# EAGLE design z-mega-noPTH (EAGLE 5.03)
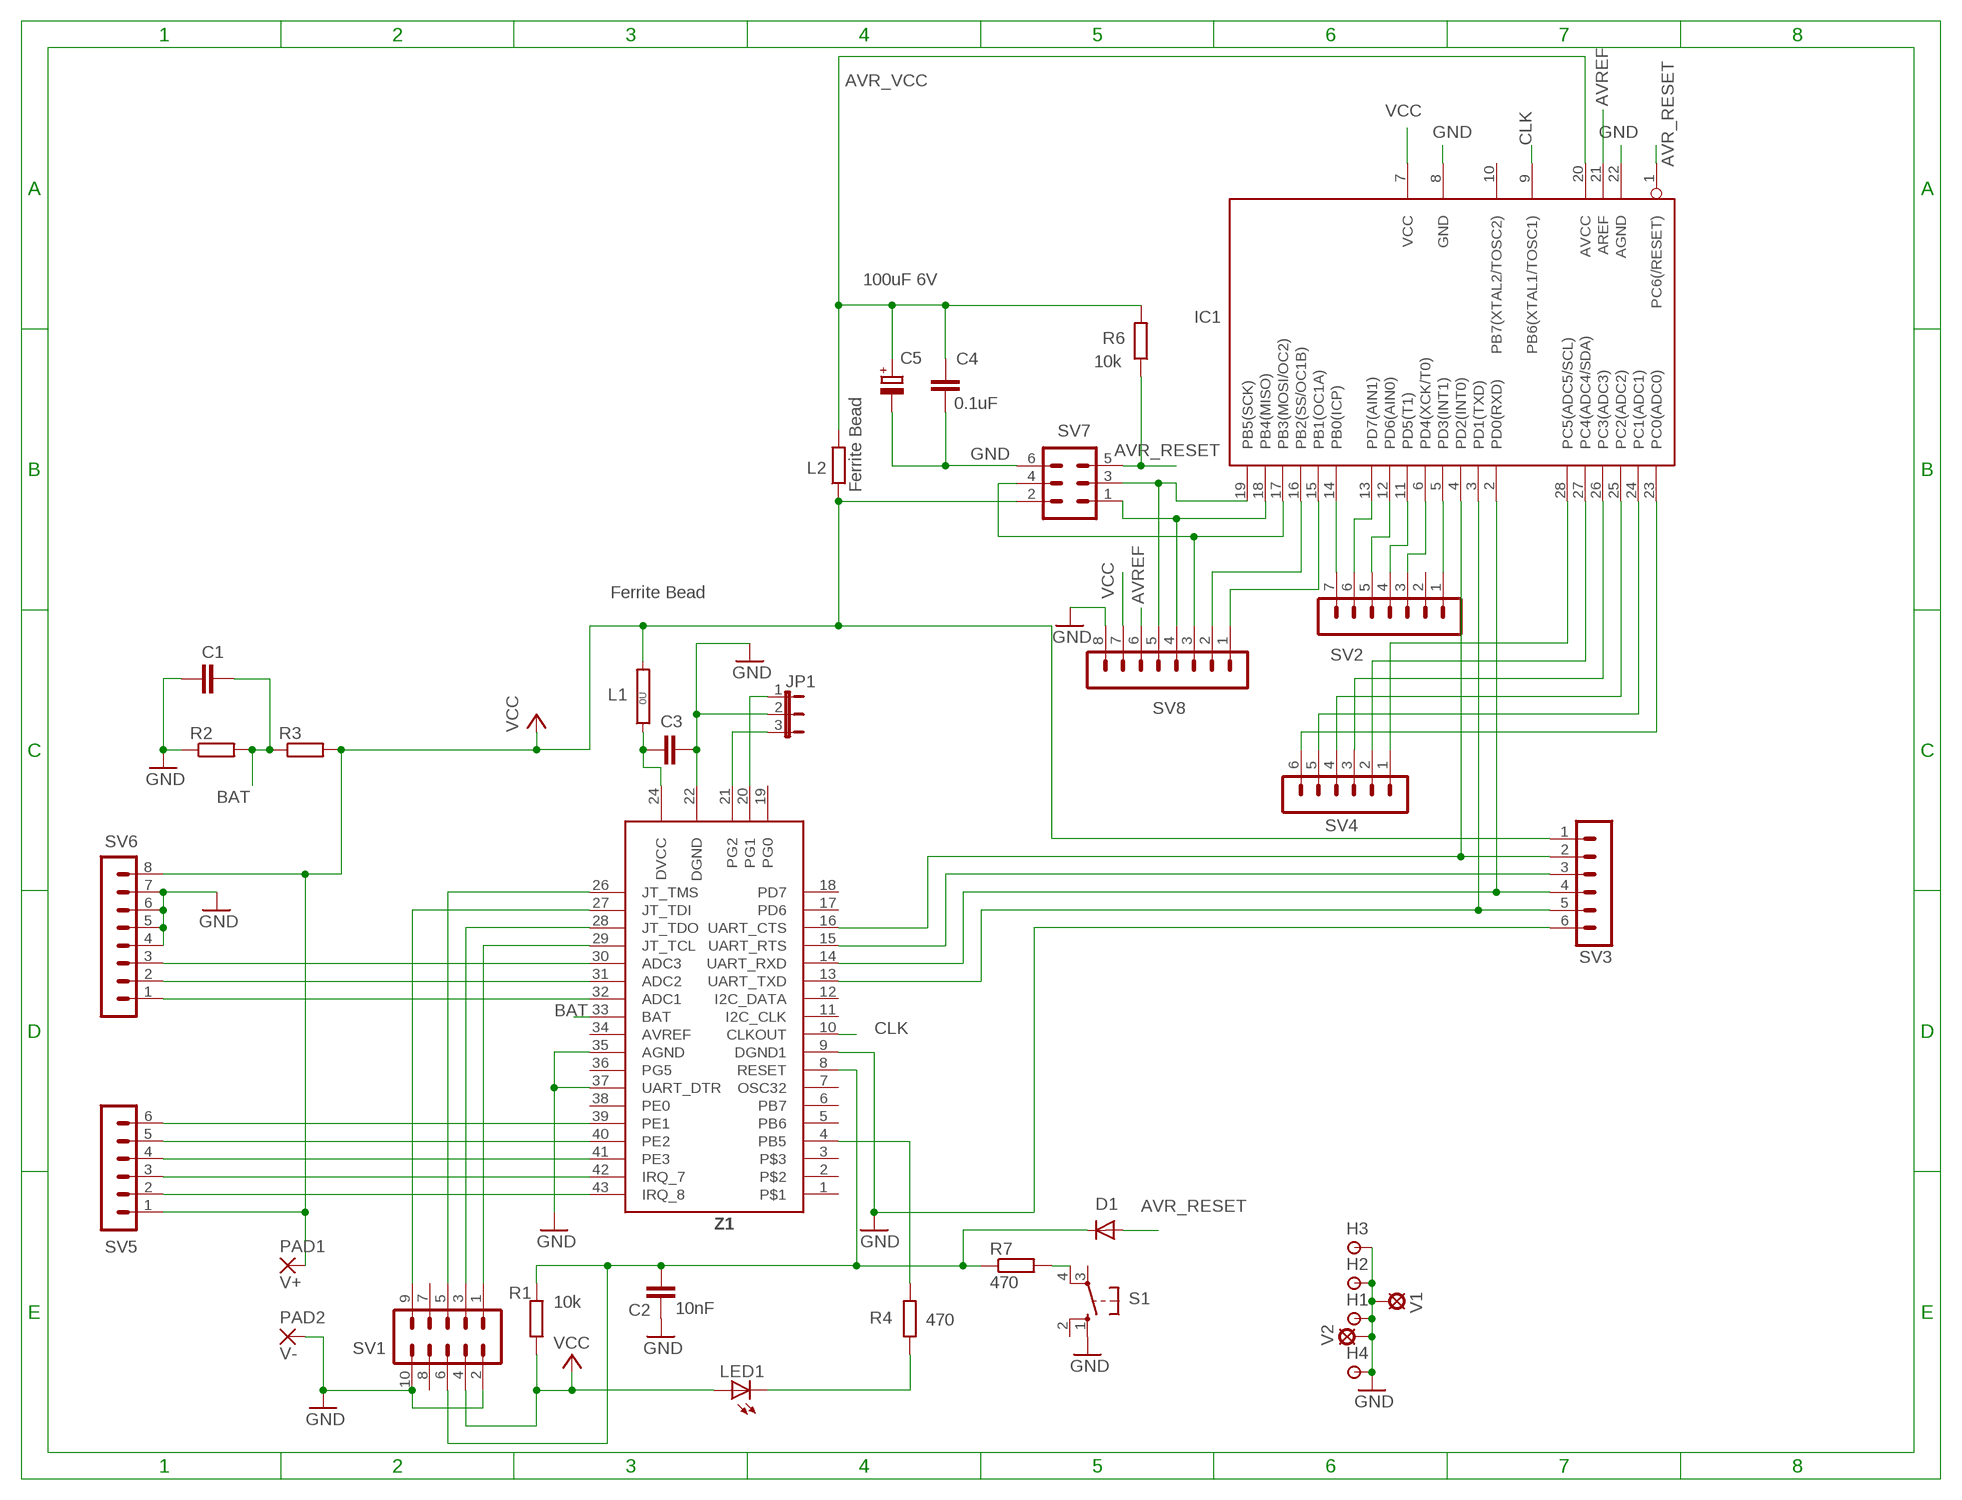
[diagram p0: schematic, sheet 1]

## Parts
C1  0.1uF  C5P  [C050-030-075]
C2  10nF  C5P  [C050-030-075]
C3  10uF 10V ceramic  CSMT0805  [C0805]
C4  0.1uF  C2.5P  [C025-030X050]
C5  100uF 6V  CPOL1  [E2,5-7---100UF]
D1  1N4148  DIODE-DO07  [DO07]
H1  HOLE/SMALL  [1,6/0,8]
H2  HOLE/SMALL  [1,6/0,8]
H3  HOLE/SMALL  [1,6/0,8]
H4  HOLE/SMALL  [1,6/0,8]
IC1  MEGA8-P  [DIL28-3]
JP1  3 way pin header with jumper  JP2E  [JP2]
L1  Ferrite Bead  0R  [0R/10]
L2  Ferrite Bead  R  [0207/10]
LED1  LED-3MM3MM  [HLMP-D105]
PAD1  V+  TERMINAL-PAD  [2,54/1,1]
PAD2  V-  TERMINAL-PAD  [2,54/1,1]
R1  10k  R  [0207/10]
R2  11k  R  [0207/10]
R3  22k  R  [0207/10]
R4  470  R  [0207/10]
R6  10k  R  [0207/10]
R7  470  R  [0207/10]
S1  PCB pushbutton BW3-1000  10-XX  [B3F-10XX]
SV1  10 way IDC male header  ML10  [ML10]
SV2  7 way header top side  MA07-1  [MA07-1]
SV3  6 way pin header top side, soldered both sides  MA06-1  [MA06-1]
SV4  6 way pin header top side  MA06-1  [MA06-1]
SV5  5 way pin header bottom mnt  MA06-1  [MA06-1]
SV6  8 way pin header bottom mnt  MA08-1  [MA08-1]
SV7  6 way male IDC header  ML6  [ML6]
SV8  8 way pin header top side  MA08-1  [MA08-1]
V1  HOLE/VIA  [LSP10]
V2  HOLE-VIA  [LSP10]
Z1  ZDM-A1281-A2N  [ZIGSMD]

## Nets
AVR_RESET: D1.A IC1.1(PC6(/RESET)) R6.1 SV7.5
AVR_VCC: C4.1 C5.+ IC1.20(AVCC) L2.2 R6.2
AVREF: IC1.21(AREF) SV8.6
BAT: C1.2 R2.2 R3.1 Z1.33(BAT)
CLK: IC1.9(PB6(XTAL1/TOSC1)) Z1.10(CLKOUT)
GND [supply]: C1.1 C2.1 C3.2 C4.2 C5.- H1.1(P) H2.1(P) H3.1(P) H4.1(P) IC1.8(GND) IC1.22(AGND) JP1.2 PAD2.1(P) R2.1 S1.1(S) SV1.2 SV1.10 SV3.6 SV6.4 SV6.5 SV6.6 SV6.7 SV7.6 SV8.8 V1.MP V2.MP Z1.9(DGND1) Z1.22(DGND) Z1.35(AGND) Z1.37(UART_DTR)
N$1: IC1.18(PB4(MISO)) SV7.1 SV8.4
N$2: IC1.19(PB5(SCK)) SV7.3 SV8.5
N$3: SV6.2 Z1.31(ADC2)
N$4: SV6.3 Z1.30(ADC3)
N$5: SV6.1 Z1.32(ADC1)
N$6: R7.2 S1.4(P1)
N$7: SV5.4 Z1.41(PE3)
N$8: IC1.17(PB3(MOSI/OC2)) SV7.4 SV8.3
N$9: SV1.5 Z1.26(JT_TMS)
N$10: SV1.1 Z1.29(JT_TCL)
N$11: SV1.3 Z1.28(JT_TDO)
N$12: SV5.6 Z1.39(PE1)
N$13: C2.2 D1.C R1.2 R7.1 SV1.6 Z1.8(RESET)
N$14: SV5.3 Z1.42(IRQ_7)
N$15: SV5.2 Z1.43(IRQ_8)
N$16: IC1.23(PC0(ADC0)) SV4.6
N$17: IC1.24(PC1(ADC1)) SV4.5
N$18: IC1.4(PD2(INT0)) SV3.2 Z1.16(UART_CTS)
N$19: SV3.3 Z1.15(UART_RTS)
N$20: IC1.2(PD0(RXD)) SV3.4 Z1.14(UART_RXD)
N$21: IC1.3(PD1(TXD)) SV3.5 Z1.13(UART_TXD)
N$24: IC1.25(PC2(ADC2)) SV4.4
N$25: JP1.1 Z1.20(PG1)
N$28: R4.2 Z1.4(PB5)
N$29: JP1.3 Z1.21(PG2)
N$30: LED1.K(C) R4.1
N$31: SV1.9 Z1.27(JT_TDI)
N$32: SV5.5 Z1.40(PE2)
N$33 [supply]: C3.1 L1.1 Z1.24(DVCC)
N$34: IC1.26(PC3(ADC3)) SV4.3
N$35: IC1.27(PC4(ADC4/SDA)) SV4.2
N$36: IC1.28(PC5(ADC5/SCL)) SV4.1
N$37: IC1.5(PD3(INT1)) SV2.1
N$38: IC1.15(PB1(OC1A)) SV8.1
N$39: IC1.16(PB2(SS/OC1B)) SV8.2
N$40: IC1.12(PD6(AIN0)) SV2.5
N$41: IC1.13(PD7(AIN1)) SV2.6
N$42: IC1.14(PB0(ICP)) SV2.7
N$44: IC1.6(PD4(XCK/T0)) SV2.3
N$45: IC1.11(PD5(T1)) SV2.4
VCC: IC1.7(VCC) L1.2 L2.1 LED1.A PAD1.1(P) R1.1 R3.2 SV1.4 SV3.1 SV5.1 SV6.8 SV7.2 SV8.7
Unconnected: IC1.10(PB7(XTAL2/TOSC2)) S1.2(S1) S1.3(P) SV1.7 SV1.8 SV2.2 Z1.1 Z1.2 Z1.3 Z1.5(PB6) Z1.6(PB7) Z1.7(OSC32) Z1.11(I2C_CLK) Z1.12(I2C_DATA) Z1.17(PD6) Z1.18(PD7) Z1.19(PG0) Z1.34(AVREF) Z1.36(PG5) Z1.38(PE0)

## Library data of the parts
C1-C4 = ee2parts:C: Capacitor
C5 = ee2parts:CPOL: Electrolytic (polarised) capacitor
D1 = diode:DIODE-: DIODE
H1-H4 = ee2parts:HOLE/SMALL: SMALL THROUGH-HOLE PAD/TESTPOINT
IC1 = atmel:MEGA8-P: MICROCONTROLLER 8 Kbytes FLASH, 1 kbytes SRAM, 512 bytes EEPROM, USART, 4-channel 10 bit ADC, 2-channel 8 bit ADC Pin compatible with Atmega48, ATMega88, ATMega168 Source: avr.lbr
JP1 = jumper:JP2E: JUMPER
L1 = jumper:0R: Bridge 0R 10mm
L2 R1-R4 R6 R7 = ee2parts:R: Resistor
LED1 = ee2parts:LED-3MM: LED
PAD1 PAD2 = ee2parts:TERMINAL-PAD: LARGE THROUGH-HOLE PAD
S1 = switch-omron:10-XX: OMRON SWITCH
SV1 = con-harting-ml:ML10: HARTING
SV2 = con-lstb:MA07-1: PIN HEADER
SV3-SV5 = con-lstb:MA06-1: PIN HEADER
SV6 SV8 = con-lstb:MA08-1: PIN HEADER
SV7 = con-harting-ml:ML6: HARTING
V1 = ee2parts:HOLE/VIA: FIXED VIA
V2 = ee2parts:HOLE-VIA: FIXED VIA
Z1 = ee2parts:ZDM-A1281-A2

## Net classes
1 supply: width 0.635 mm

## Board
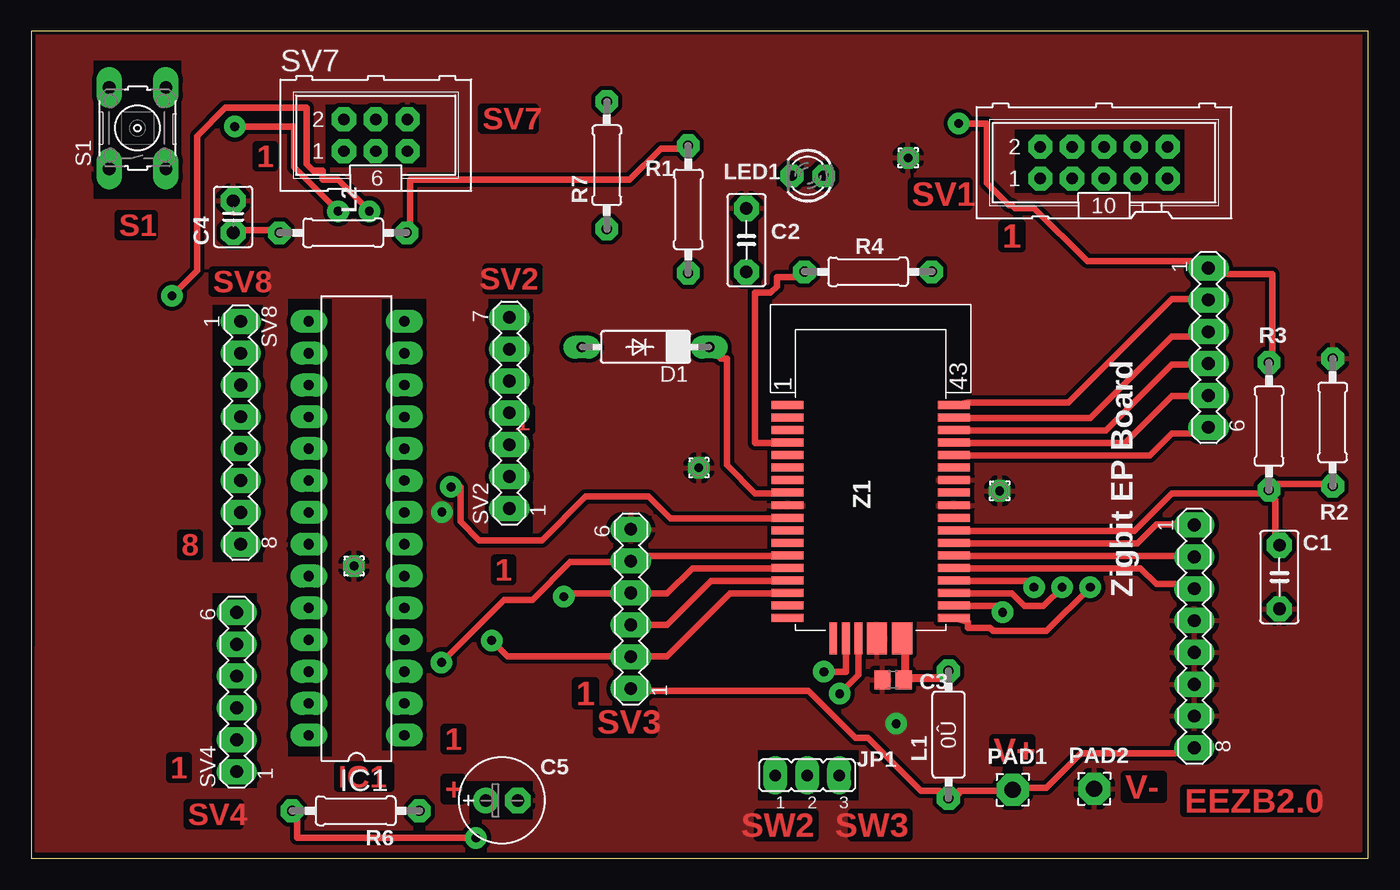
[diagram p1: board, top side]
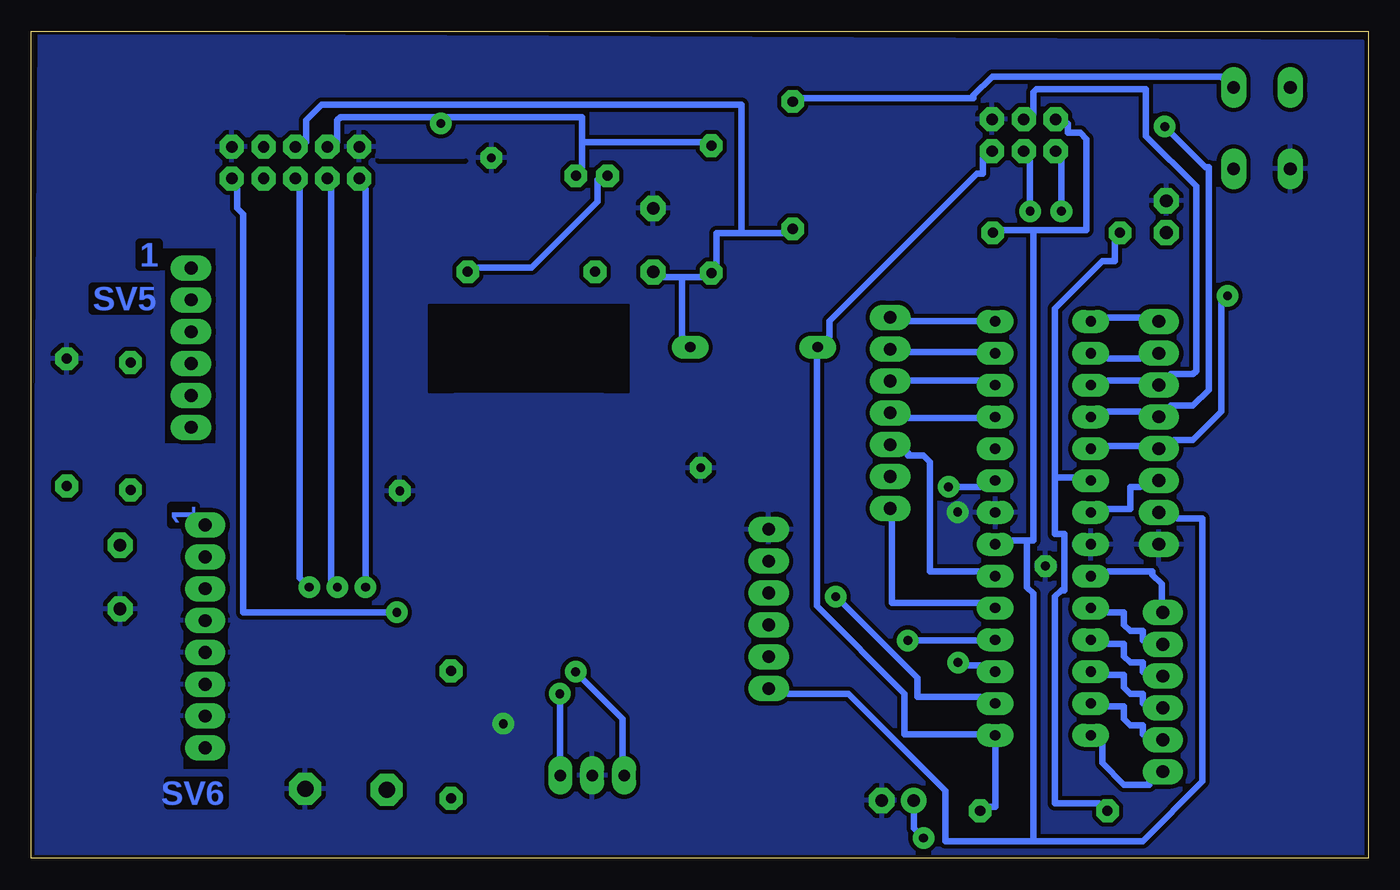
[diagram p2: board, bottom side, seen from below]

Size 106.63 x 65.98 mm. Coordinates in mm from the lower left corner, seen from the top.
Outline: 0,0 106.63,0 106.63,65.98 0,65.98 0,0
Copper layers (1*16): Top 0.035mm / dielectric 1.5mm / Bottom 0.035mm
Design rules "zigbit_rules *": minimum track width 20mil, minimum drill 0.7mm, track to track 13mil, track to pad 13mil, pad to pad 13mil, via to via 13mil, smd to smd 0mil, copper to edge 10mil, drill to drill 10mil, minimum pad ring 20mil, minimum via ring 20mil, stop-mask expansion 0mil, vias tented up to drill 0mil, thermal gap 15mil
tRestrict: area 78.5,53.1 to 92,58.1; area 59.5,53.6 to 64,55.1; area 56,45.6 to 58,52.6; area 58,4.6 to 66,8.6; area 20.5,8.1 to 24,44.6; area 28,8.6 to 31.5,44.6; area 23.5,55.1 to 31.5,60.1; area 14.5,23.6 to 18.5,44.1; area 14.5,5.6 to 18,21.1; area 36.5,26.1 to 40,44.6; area 35,3.1 to 40,6.1; area 5,52.6 to 12,63.6
bRestrict: area 92,33.1 to 96,48.6; area 91,7.1 to 94.5,27.1; 1 lines
vRestrict: area 75,50.1 to 97,60.6; area 19,52.6 to 35.5,62.6

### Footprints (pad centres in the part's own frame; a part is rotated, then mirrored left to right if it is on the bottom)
C050-030-075 = drill 1 octagon: 1 -2.54,0; 2 2.54,0
C0805 = smd 1.3 x 1.5: 1 -0.85,0; 2 0.85,0
C025-030X050 = drill 1 octagon: 1 -1.27,0; 2 1.27,0
E2,5-7---100UF = drill 1 pad 1.6 round: + -1.27,0 | drill 1 pad 1.6 octagon: - 1.27,0
DO07 = drill 0.813 long: A 5.08,0; C -5.08,0
1,6/0,8 = drill 0.7 pad 1.6 octagon: 1 0,0
DIL28-3 = drill 0.813 long: 1 -16.51,-3.81; 2 -13.97,-3.81; 3 -11.43,-3.81; 4 -8.89,-3.81; 5 -6.35,-3.81; 6 -3.81,-3.81; 7 -1.27,-3.81; 8 1.27,-3.81; 9 3.81,-3.81; 10 6.35,-3.81; 11 8.89,-3.81; 12 11.43,-3.81; 13 13.97,-3.81; 14 16.51,-3.81; 15 16.51,3.81; 16 13.97,3.81; 17 11.43,3.81; 18 8.89,3.81; 19 6.35,3.81; 20 3.81,3.81; 21 1.27,3.81; 22 -1.27,3.81; 23 -3.81,3.81; 24 -6.35,3.81; 25 -8.89,3.81; 26 -11.43,3.81; 27 -13.97,3.81; 28 -16.51,3.81
JP2 = drill 0.914 long: 1 -2.54,0; 2 0,0; 3 2.54,0
0R/10 = drill 0.813 pad 1.6 octagon: 1 -5.08,0; 2 5.08,0
0207/10 = drill 0.8 octagon: 1 -5.08,0; 2 5.08,0
HLMP-D105 = drill 0.8 octagon: A -1.27,0; K 1.27,0
2,54/1,1 = drill 1.3 pad 2.54 octagon: 1 0,0
B3F-10XX = drill 1.016 long: 1 -3.251,2.261; 2 3.251,2.261; 3 -3.251,-2.261; 4 3.251,-2.261
ML10 = drill 0.914 octagon: 1 -5.08,-1.27; 2 -5.08,1.27; 3 -2.54,-1.27; 4 -2.54,1.27; 5 0,-1.27; 6 0,1.27; 7 2.54,-1.27; 8 2.54,1.27; 9 5.08,-1.27; 10 5.08,1.27
MA07-1 = drill 1.016 long: 1 -7.62,0; 2 -5.08,0; 3 -2.54,0; 4 0,0; 5 2.54,0; 6 5.08,0; 7 7.62,0
MA06-1 = drill 1.016 long: 1 -6.35,0; 2 -3.81,0; 3 -1.27,0; 4 1.27,0; 5 3.81,0; 6 6.35,0
MA08-1 = drill 1.016 long: 1 -8.89,0; 2 -6.35,0; 3 -3.81,0; 4 -1.27,0; 5 1.27,0; 6 3.81,0; 7 6.35,0; 8 8.89,0
ML6 = drill 0.914 octagon: 1 -2.54,-1.27; 2 -2.54,1.27; 3 0,-1.27; 4 0,1.27; 5 2.54,-1.27; 6 2.54,1.27
LSP10 = drill 0.7 pad 1.016 round: MP 0,0
ZIGSMD = smd 0.635 x 2.54: 1 7,6.635; 2 6,6.635; 3 5,6.635; 4 4,6.635; 5 3,6.635; 6 2,6.635; 7 1,6.635; 8 0,6.635; 9 -1,6.635; 10 -2,6.635; 11 -3,6.635; 12 -4,6.635; 13 -5,6.635; 14 -6,6.635; 15 -7,6.635; 16 -8,6.635; 17 -9,6.635; 18 -10,6.635; 26 -10,-6.635; 27 -9,-6.635; 28 -8,-6.635; 29 -7,-6.635; 30 -6,-6.635; 31 -5,-6.635; 32 -4,-6.635; 33 -3,-6.635; 34 -2,-6.635; 35 -1,-6.635; 36 0,-6.635; 37 1,-6.635; 38 2,-6.635; 39 3,-6.635; 40 4,-6.635; 41 5,-6.635; 42 6,-6.635; 43 7,-6.635 | smd 2.54 x 0.635: 19 -11.635,3; 20 -11.635,2; 21 -11.635,1 | smd 2.54 x 1.6: 22 -11.635,-0.5; 24 -11.635,-2.5

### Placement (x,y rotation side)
C1  99.55,22.44 90 top
C2  57.04,49.32 270 top
C3  68.74,14.25 180 top
C4  16.1,51.19 90 top
C5  37.53,4.62 0 top
D1  48.99,40.79 180 top
H1  77.24,29.32 0 top
H2  69.94,55.89 0 top
H3  53.24,31.16 0 top
H4  25.74,23.32 0 top
IC1  25.94,26.33 90 top
JP1  61.89,6.62 0 top
L1  73.16,9.87 270 top
L2  24.87,49.91 180 top
LED1  61.93,54.45 180 top
PAD1  78.28,5.47 0 top
PAD2  84.78,5.55 0 top
R1  52.39,51.78 270 top
R2  103.8,34.78 270 top
R3  98.72,34.48 90 top
R4  66.74,46.8 180 top
R6  25.87,3.79 180 top
R7  45.9,55.3 90 top
S1  8.47,58.26 90 top
SV1  85.56,55.5 0 top
SV2  38.13,35.54 90 top
SV3  47.82,19.9 90 top
SV4  16.37,13.27 90 top
SV5  93.89,40.74 270 top
SV6  92.77,17.7 270 top
SV7  27.47,57.69 0 top
SV8  16.69,33.95 270 top
V1  32.74,27.63 0 top
V2  68.99,10.74 0 top
Z1  66.96,29.17 90 top

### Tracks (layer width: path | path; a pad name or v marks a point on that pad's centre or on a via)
AVR_RESET
  Bottom 0.508: R6.1 30.22,4.13 29.72,4.13 29.72,9.13 IC1.1 30.97,9.88 36.97,9.88 36.97,13.13 43.97,20.13 43.97,39.88 D1.A 42.97,41.63 42.97,42.88 31.22,54.63 30.72,54.63 30.72,55.88 SV7.5
AVR_VCC  (via drill 0.7)
  Top 0.508: v35.47,1.63 21.22,1.63 21.22,3.13 R6.2 | L2.2 18.97,50.13 16.97,50.13 C4.1
  Bottom 0.508: v35.47,1.63 36.22,2.38 36.22,3.63 C5.+ | 24.97,30.38 23.47,30.38 IC1.20 | 24.97,30.38 24.97,43.88 21.22,47.63 20.22,47.63 20.22,49.13 L2.2 | R6.2 21.47,4.38 24.97,4.38 24.97,20.88 24.47,21.38 24.22,21.38 24.22,25.88 24.97,25.88 24.97,30.38
AVREF
  Bottom 0.508: IC1.21 20.72,27.88 18.97,27.88 18.97,29.63 18.22,29.63 SV8.6
BAT
  Top 0.508: Z1.33 74.72,26.13 87.97,26.13 90.97,29.13 97.97,29.13 R3.1 | R2.2 102.97,29.88 99.47,29.88 R3.1 | C1.2 99.22,25.88 99.22,28.63 R3.1
CLK  (via drill 0.7)
  Top 0.508: v33.47,29.63 34.22,29.63 34.22,26.88 35.72,25.38 40.72,25.38 44.22,28.88 49.22,28.88 50.97,27.13 59.22,27.13 Z1.10
  Bottom 0.508: v33.47,29.63 30.97,29.63 IC1.9
GND
  pour Top: 0.53,65.63 105.97,65.63 105.97,0.63 0.47,0.63
  pour Bottom: 0.47,65.13 105.97,65.63 106.47,0.13 0.47,0.13
N$1  (via drill 0.7)
  Top 0.508: v24.47,51.63 20.97,55.13 20.97,58.38 v16.22,58.38
  Bottom 0.508: IC1.18 20.72,35.63 18.22,35.63 SV8.4 15.72,36.13 13.97,36.13 12.72,37.38 12.72,55.13 12.97,55.13 v16.22,58.38 | v24.47,51.63 24.47,55.63 SV7.1
N$2  (via drill 0.7)
  Top 0.508: v26.97,51.63 24.47,54.13 23.22,54.13 23.22,54.88 22.47,54.88 21.97,55.38 21.97,59.88 15.47,59.88 13.22,57.63 13.22,46.88 v11.22,44.88
  Bottom 0.508: IC1.19 20.72,32.88 18.22,32.88 SV8.5 15.47,33.38 13.97,33.38 11.72,35.63 11.72,44.38 v11.22,44.88 | v26.97,51.63 26.97,55.63 SV7.3
N$3
  Top 0.508: Z1.31 74.72,24.13 91.22,24.13 SV6.2
N$4
  Top 0.508: Z1.30 74.72,23.13 88.47,23.13 89.72,21.88 91.22,21.88 SV6.3
N$5
  Top 0.508: Z1.32 74.72,25.13 88.22,25.13 89.72,26.63 91.22,26.63 SV6.1
N$6
  Bottom 0.508: R7.2 45.22,60.63 31.47,60.63 31.47,60.88 29.97,62.38 11.72,62.38 S1.4
N$7
  Top 0.508: Z1.41 74.72,34.13 85.72,34.13 90.97,39.38 92.47,39.38 SV5.4
N$8
  Bottom 0.508: IC1.17 20.72,38.13 18.22,38.13 SV8.3 15.72,38.63 13.97,38.63 13.72,38.88 13.72,53.63 17.72,57.63 17.72,61.38 26.47,61.38 26.72,61.13 26.72,59.38 SV7.4
N$9  (via drill 0.7)
  Top 0.508: v84.47,21.63 80.97,18.13 76.72,18.13 76.47,18.38 74.72,18.38 74.72,18.88 Z1.26
  Bottom 0.508: v84.47,21.63 85.22,22.38 85.22,53.38 SV1.5
N$10  (via drill 0.7)
  Top 0.508: v79.97,21.63 79.47,22.13 74.72,22.13 Z1.29
  Bottom 0.508: v79.97,21.63 79.97,53.38 SV1.1
N$11  (via drill 0.7)
  Top 0.508: v82.22,21.63 80.72,20.13 79.22,20.13 78.22,21.13 74.72,21.13 Z1.28
  Bottom 0.508: v82.22,21.63 82.72,22.13 82.72,53.38 SV1.3
N$12
  Top 0.508: Z1.39 74.72,32.13 89.22,32.13 90.97,33.88 92.47,33.88 SV5.6
N$13
  Top 0.508: Z1.8 59.22,29.13 57.72,29.13 55.47,31.38 55.47,39.88 54.97,39.88 D1.C
  Bottom 0.508: 54.72,46.38 56.22,46.38 C2.2 | 54.72,46.38 53.22,46.38 R1.2 51.97,47.38 51.97,49.88 49.97,49.88 | 49.97,49.88 46.72,49.88 R7.1 | SV1.6 84.72,57.13 84.72,58.88 83.47,60.13 49.97,60.13 49.97,49.88 | D1.C 54.72,41.63 54.72,46.38
N$14
  Top 0.508: Z1.42 74.72,35.13 84.47,35.13 90.97,41.63 92.47,41.63 SV5.3
N$15
  Top 0.508: Z1.43 74.72,36.38 82.72,36.38 90.97,44.63 92.47,44.63 SV5.2
N$16
  Bottom 0.508: IC1.23 20.72,22.88 17.22,22.88 17.22,22.63 16.47,21.88 16.47,20.63 SV4.6
N$17
  Bottom 0.508: IC1.24 20.72,19.63 19.47,19.63 19.47,18.63 18.97,18.13 17.97,18.13 17.97,17.38 SV4.5
N$18  (via drill 0.7)
  Top 0.508: Z1.16 59.22,21.13 55.72,21.13 50.72,16.13 49.22,16.13 SV3.2 46.22,16.13 37.97,16.13 v36.72,17.38
  Bottom 0.508: v36.72,17.38 30.97,17.38 IC1.4
N$19
  Top 0.508: Z1.15 59.22,22.13 54.22,22.13 50.72,18.63 SV3.3
N$20  (via drill 0.7)
  Top 0.508: Z1.14 59.22,23.13 52.72,23.13 50.72,21.13 49.22,21.13 SV3.4 46.22,21.13 42.72,21.13 v42.47,20.88
  Bottom 0.508: v42.47,20.88 35.97,14.38 35.97,12.88 30.97,12.88 IC1.2
N$21  (via drill 0.7)
  Top 0.508: Z1.13 59.22,24.13 49.22,24.13 SV3.5 46.22,23.63 42.97,23.63 39.97,20.63 37.72,20.63 v32.72,15.63
  Bottom 0.508: v32.72,15.63 32.72,15.38 30.97,15.38 IC1.3
N$24
  Bottom 0.508: IC1.25 20.72,17.13 19.47,17.13 19.47,16.13 18.97,15.63 17.97,15.63 17.97,14.88 SV4.4
N$25  (via drill 0.7)
  Top 0.508: v63.22,14.88 64.97,14.88 64.97,16.38 Z1.20
  Bottom 0.508: v63.22,14.88 59.47,11.13 59.47,8.13 JP1.1
N$28
  Top 0.508: Z1.4 59.22,33.13 57.72,33.13 57.72,45.13 58.97,45.13 59.47,45.63 59.47,46.38 60.97,46.38 R4.2
N$29  (via drill 0.7)
  Top 0.508: v64.47,13.13 65.97,14.63 65.97,16.38 Z1.21
  Bottom 0.508: v64.47,13.13 64.47,8.13 JP1.3
N$30
  Bottom 0.508: LED1.K 61.47,54.13 61.47,52.38 66.72,47.13 70.97,47.13 R4.1
N$31  (via drill 0.7)
  Top 0.508: v77.47,19.63 76.97,20.13 74.72,20.13 Z1.27
  Bottom 0.508: v77.47,19.63 89.72,19.63 89.72,51.38 90.22,51.88 90.22,53.38 SV1.9
N$32
  Top 0.508: Z1.40 74.72,33.13 87.22,33.13 90.97,36.88 92.47,36.88 SV5.5
N$33
  Top 0.635: Z1.24 69.72,16.38 69.72,14.88 C3.1 70.22,14.38 72.47,14.38 L1.1
N$34
  Bottom 0.508: IC1.26 20.72,14.63 19.47,14.63 19.47,13.63 18.97,13.13 17.97,13.13 17.97,12.38 SV4.3
N$35
  Bottom 0.508: IC1.27 20.72,12.13 19.47,12.13 19.47,11.13 18.97,10.63 17.97,10.63 17.97,9.88 SV4.2
N$36
  Bottom 0.508: IC1.28 21.22,9.13 21.22,7.63 19.47,5.88 17.47,5.88 17.47,6.13 SV4.1
N$37
  Bottom 0.508: IC1.5 30.97,20.38 37.97,20.38 37.97,27.13 SV2.1
N$38
  Bottom 0.508: IC1.15 20.72,43.13 18.22,43.13 SV8.1
N$39
  Bottom 0.508: IC1.16 20.72,39.88 18.22,39.88 SV8.2
N$40
  Bottom 0.508: IC1.12 30.97,38.13 36.72,38.13 SV2.5
N$41
  Bottom 0.508: IC1.13 30.97,40.38 36.72,40.38 SV2.6
N$42
  Bottom 0.508: IC1.14 30.97,42.88 36.72,42.88 SV2.7
N$44
  Bottom 0.508: IC1.6 30.97,22.88 34.97,22.88 34.97,31.63 35.47,32.13 36.72,32.13 36.72,32.38 SV2.3
N$45
  Bottom 0.508: IC1.11 30.97,35.13 36.72,35.13 SV2.4
VCC  (via drill 0.7)
  Top 0.508: SV3.1 49.22,13.38 61.97,13.38 65.72,9.63 66.72,9.63 70.97,5.38 72.47,5.38 L1.2 73.97,5.13 73.97,5.38 77.22,5.38 PAD1.1 79.47,5.63 80.97,5.63 83.72,8.38 91.22,8.38 SV6.8 | R3.2 98.97,40.38 98.97,46.63 95.47,46.63 SV5.1 92.47,47.63 84.22,47.63 79.97,51.88 78.47,51.88 78.22,52.13 77.97,52.13 76.22,53.88 76.22,58.63 v73.97,58.63 | L2.1 30.22,50.63 30.22,54.13 47.72,54.13 50.22,56.63 51.72,56.63 R1.1
  Bottom 0.508: 26.72,1.38 33.72,1.38 33.72,5.38 41.47,13.13 46.22,13.13 SV3.1 | 26.72,1.38 17.97,1.38 13.22,6.13 13.22,27.13 15.22,27.13 SV8.7 | 26.72,50.13 22.47,50.13 22.47,57.38 22.97,57.88 23.97,57.88 23.97,58.63 SV7.2 | 26.72,50.13 29.22,50.13 L2.1 | 27.22,25.38 26.72,25.38 26.72,50.13 | 27.22,25.38 28.47,25.38 IC1.7 | 62.72,57.13 53.22,57.13 R1.1 | 62.72,57.13 62.72,55.13 LED1.A | 73.97,59.13 62.72,59.13 62.72,57.13 | 73.97,59.13 81.97,59.13 82.22,58.88 82.22,57.13 SV1.4 | 73.97,59.13 v73.97,58.63 | 26.72,1.38 26.72,21.13 27.22,21.63 27.22,25.38

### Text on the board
Top: SV7 | 1 | 1 | S1 | SV2 | SV8 | 1 | 8 | 1 | 1 | 1 | 1 | IC1 | + | SW2 | SW3 | EEZB2.0 | SV4
Bottom: 1 | 1
tPlace: Zigbit EP Board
